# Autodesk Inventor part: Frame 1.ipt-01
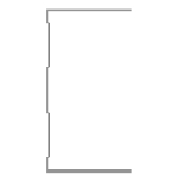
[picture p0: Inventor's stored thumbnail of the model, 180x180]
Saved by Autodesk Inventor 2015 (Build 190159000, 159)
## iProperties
Created: 2015-04
Part Number: Frame 1.ipt-01
Material: Aluminum 6061
Description: Kévin Novo
Document SubType Name: Modeling
Standard: Kevin
Designer: suporte
Standards Organization: Kevin
Language: en-US
Size Designation: (Unnamed 1)
Categories: <MemberInstance><Categories><Category DisplayName="Structural Shapes" InternalName="089c4875-fa83-4c05-b084-43b9cc11f5ed" Mnemonic="GRDR"><CategoryParameter Dis
Density: 2.7 g/cm^3
Appearance: Aluminum - Flat
IsCustomPart: 1
_CCFamilyMember: 1
_CCFamilyDisplayName: Kévin - Kévin Novo
_FrameMemberDoc: Frame Member File
_Version: 15.0.0
_GetPNFromCC: 1
G_L: 2100,000 mm
G_W: 50,000 mm
G_H: 75,000 mm
+908A4224-EE65-46DC-B71A-C79DF3732D37+CUTDETAIL1: Notch
Author: suporte
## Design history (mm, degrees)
node "Start Plane"
node "End Plane"
sketch "Sketch"
  geometry: L1 (24.7, 37.5)-(24.7, 36.9); L2 (24.7, 36.9)-(-24.7, 36.9); L3 (-24.7, -36.9)-(24.7, -36.9); L4 (24.7, -36.9)-(24.7, -37.5); L5 (24.7, -37.5)-(-25.3, -37.5); L6 (-25.3, 37.5)-(24.7, 37.5); L7 (-24.7, 36.9)-(-24.7, 31.9); L8 (-24.7, 31.9)-(-23.3, 30.5); L9 (-23.3, 30.5)-(-23.3, 10.934); L10 (-23.3, 10.934)-(-24.7, 9.534); L11 (-24.7, 9.534)-(-24.7, -9.534); L12 (-24.7, -9.534)-(-23.3, -10.934); L13 (-23.3, -10.934)-(-23.3, -30.5); L14 (-23.3, -30.5)-(-24.7, -31.9); L15 (-24.7, -31.9)-(-24.7, -36.9); L16 (-25.3, -37.5)-(-25.3, -31.651); L17 (-25.3, -31.651)-(-23.9, -30.251); L18 (-23.9, -30.251)-(-23.9, -11.183); L19 (-23.9, -11.183)-(-25.3, -9.783); L20 (-25.3, -9.783)-(-25.3, 9.783); L21 (-25.3, 9.783)-(-23.9, 11.183); L22 (-23.9, 11.183)-(-23.9, 30.251); L23 (-23.9, 30.251)-(-25.3, 31.651); L24 (-25.3, 31.651)-(-25.3, 37.5); L25 (-25.3, 0)-(30.37, 0); 3 further points
  constraints: 50 end point, 10 point on line, 9 parallel, 5 perpendicular, 4 equal length, 3 midpoint, 3 vertical, 2 vertical alignment, 1 collinear, 1 horizontal, 1 horizontal alignment
  dimensions: "d3" = 0.6 distance of L1.start L1.end (= d6); "d5" = 75 distance between parallel lines of L5 L6; "d6" = 0.6 distance between parallel lines of L24 L7 (= d8); "d7" = 0.6 distance between parallel lines of L8 L23 (= d8); "d8" = 0.6 distance between parallel lines of L22 L9 (= d12); "Espessura" = 0.6 distance between parallel lines of L17 L14; "d10" = 0.6 distance between parallel lines of L13 L18 (= Espessura); "d11" = 0.6 distance between parallel lines of L12 L19 (= Espessura); "d12" = 0.6 distance between parallel lines of L21 L10 (= d11); "d13" = 5 distance of L2.end L7.end; "d15" = 135 deg angle of L9 L8; "d16" = 2 distance between parallel lines of L24 L9; "d17" = 50 distance of L6.start L1.start
extrude "Body" join sketch "Sketch" stored distance "d24" = 0.13; taper "d25" = 0 deg
node "Driven Length"
  sketch "Sketch10"
    geometry: L1 (0, 0)-(10, 0) reference
    constraints: 2 end point, 1 horizontal
  workplane "Work Plane7"
  sketch "Sketch11"
    geometry: L1 (-2, 0)-(12, 0) reference; L2 (-2, 2100)-(12, 2100) reference
    dimensions: "d27" = 2100 distance between parallel lines of L1 L2 (derived)
workplane "Work Plane8"
workplane "Work Plane9"
workplane "Work Plane10"
sketch "Sketch12"
  geometry: L1 (24.7, 37.5)-(24.7, 36.9); L2 (24.7, 36.9)-(-24.7, 36.9); L3 (-24.7, 36.9)-(-24.7, 31.9); L4 (-24.7, 31.9)-(-23.3, 30.5); L5 (-23.3, 30.5)-(-23.3, 10.934); L6 (-23.3, 10.934)-(-24.7, 9.534); L7 (-24.7, 9.534)-(-24.7, -9.534); L8 (-24.7, -9.534)-(-23.3, -10.934); L9 (-23.3, -10.934)-(-23.3, -30.5); L10 (-23.3, -30.5)-(-24.7, -31.9); L11 (-24.7, -31.9)-(-24.7, -36.9); L12 (-24.7, -36.9)-(24.7, -36.9); L13 (24.7, -36.9)-(24.7, -37.5); L14 (24.7, -37.5)-(-25.3, -37.5); L15 (-25.3, -37.5)-(-25.3, -31.651); L16 (-25.3, -31.651)-(-23.9, -30.251); L17 (-23.9, -30.251)-(-23.9, -11.183); L18 (-23.9, -11.183)-(-25.3, -9.783); L19 (-25.3, -9.783)-(-25.3, 9.783); L20 (-25.3, 9.783)-(-23.9, 11.183); L21 (-23.9, 11.183)-(-23.9, 30.251); L22 (-23.9, 30.251)-(-25.3, 31.651); L23 (-25.3, 31.651)-(-25.3, 37.5); L24 (-25.3, 37.5)-(24.7, 37.5)
  constraints: 48 end point, 10 point on line
extrude "Extrusion3" cut sketch "Sketch12" stored distance "d36" = 0.13; taper "d37" = 0 deg
body "Solid1"
other parameters: "G_OFFSET_START" = 0 [user parameter; used in 1 equation term], "G_OFFSET_END" = 0 [user parameter; used in 1 equation term], "d22" = 0 (computed from G_OFFSET_START), "G_L" = 2100 (= d27) [user parameter], "d34" = 90 deg
